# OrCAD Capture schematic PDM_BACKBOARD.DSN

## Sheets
1 bb_outline: title: Photo Detector Module's backboard; rev: 1.0; note: BB_outline; note: INFN-Ferrara / INFN Milano-Bicocca; note: designer: Angelo Cotta Ramusino
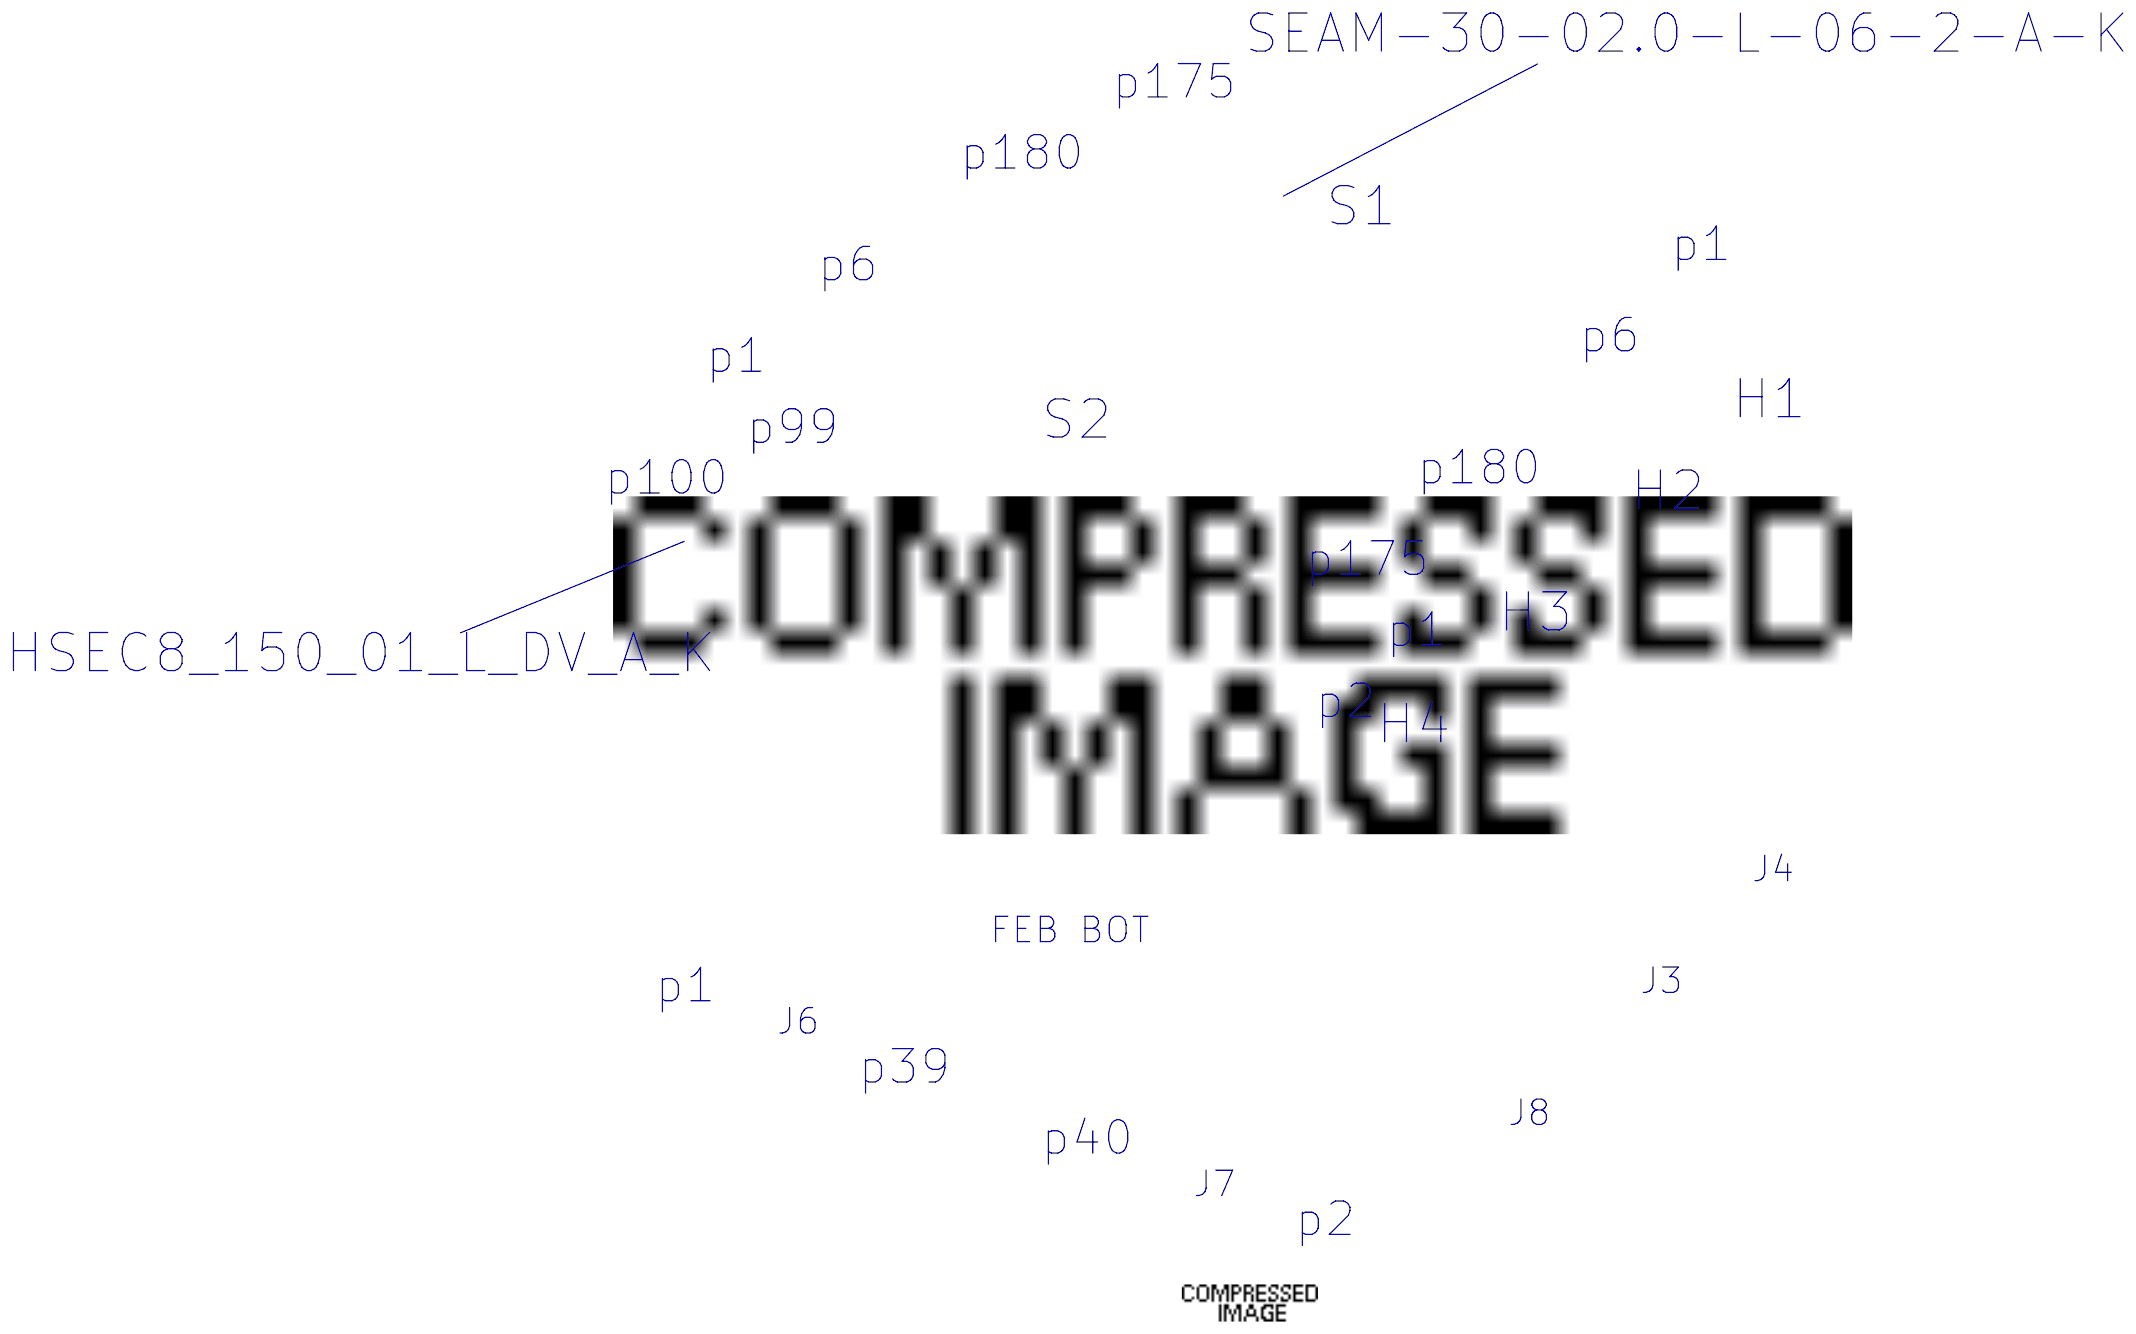
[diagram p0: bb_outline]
2 bb_main: size B; note: BB_sch_main
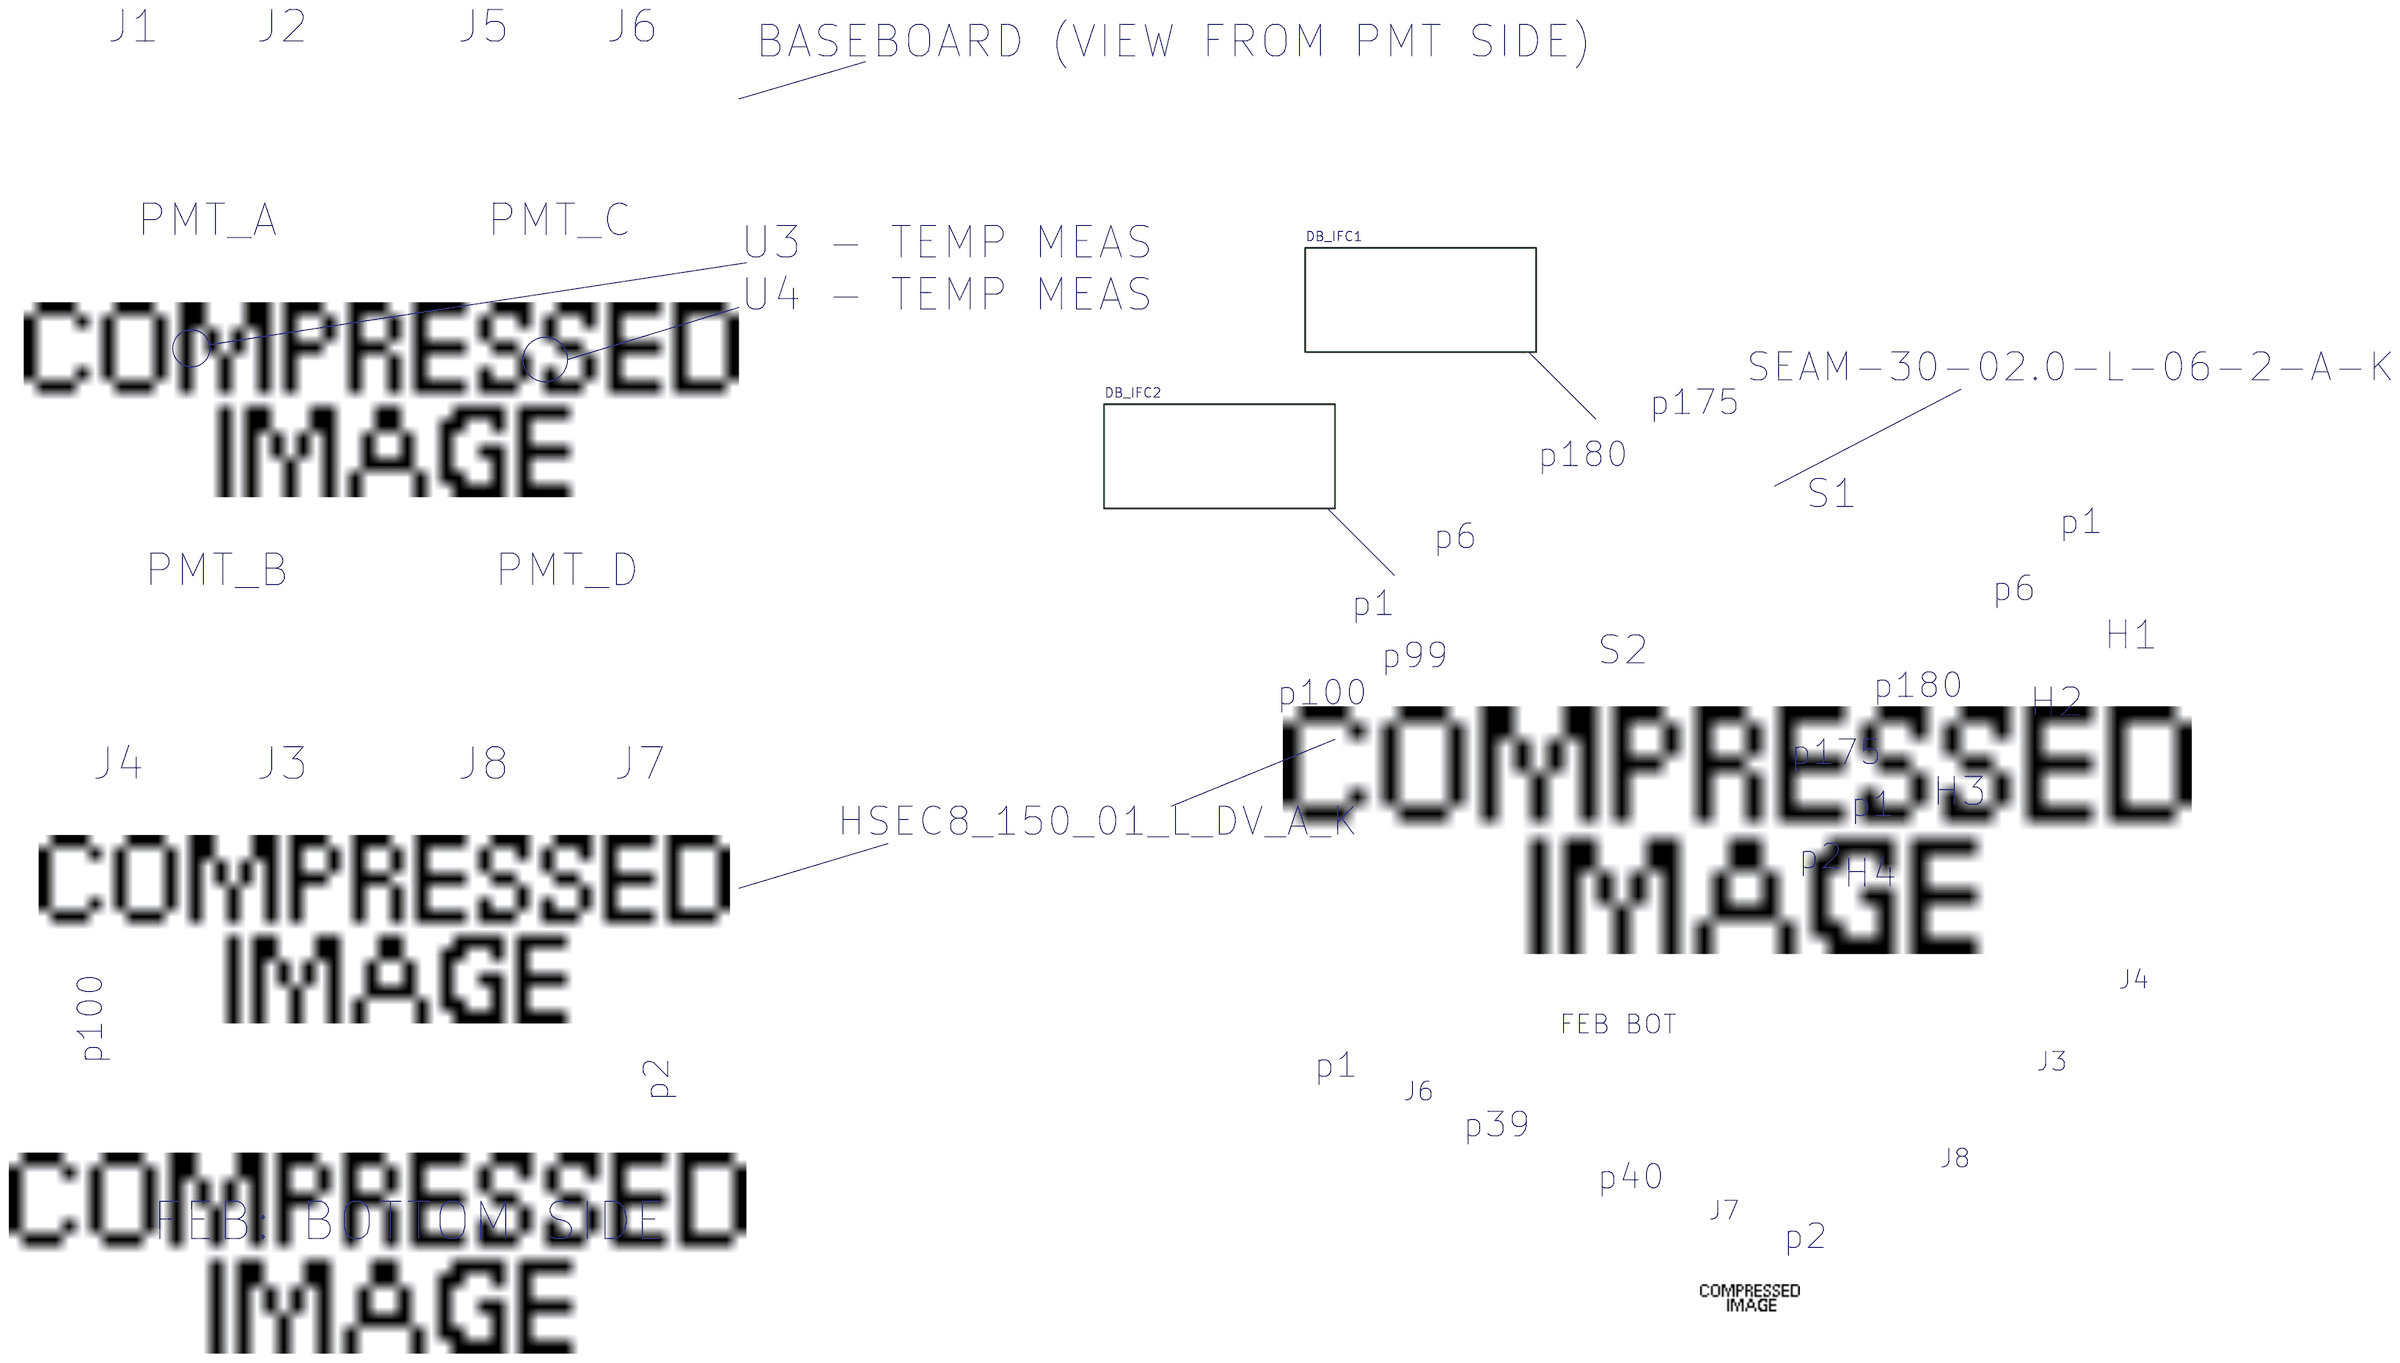
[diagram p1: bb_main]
3 DB_Interface_1: size B; note: DB_Interface_1; note: designer: A. Cotta Ramusino, C. Gotti; block DB_IFC1
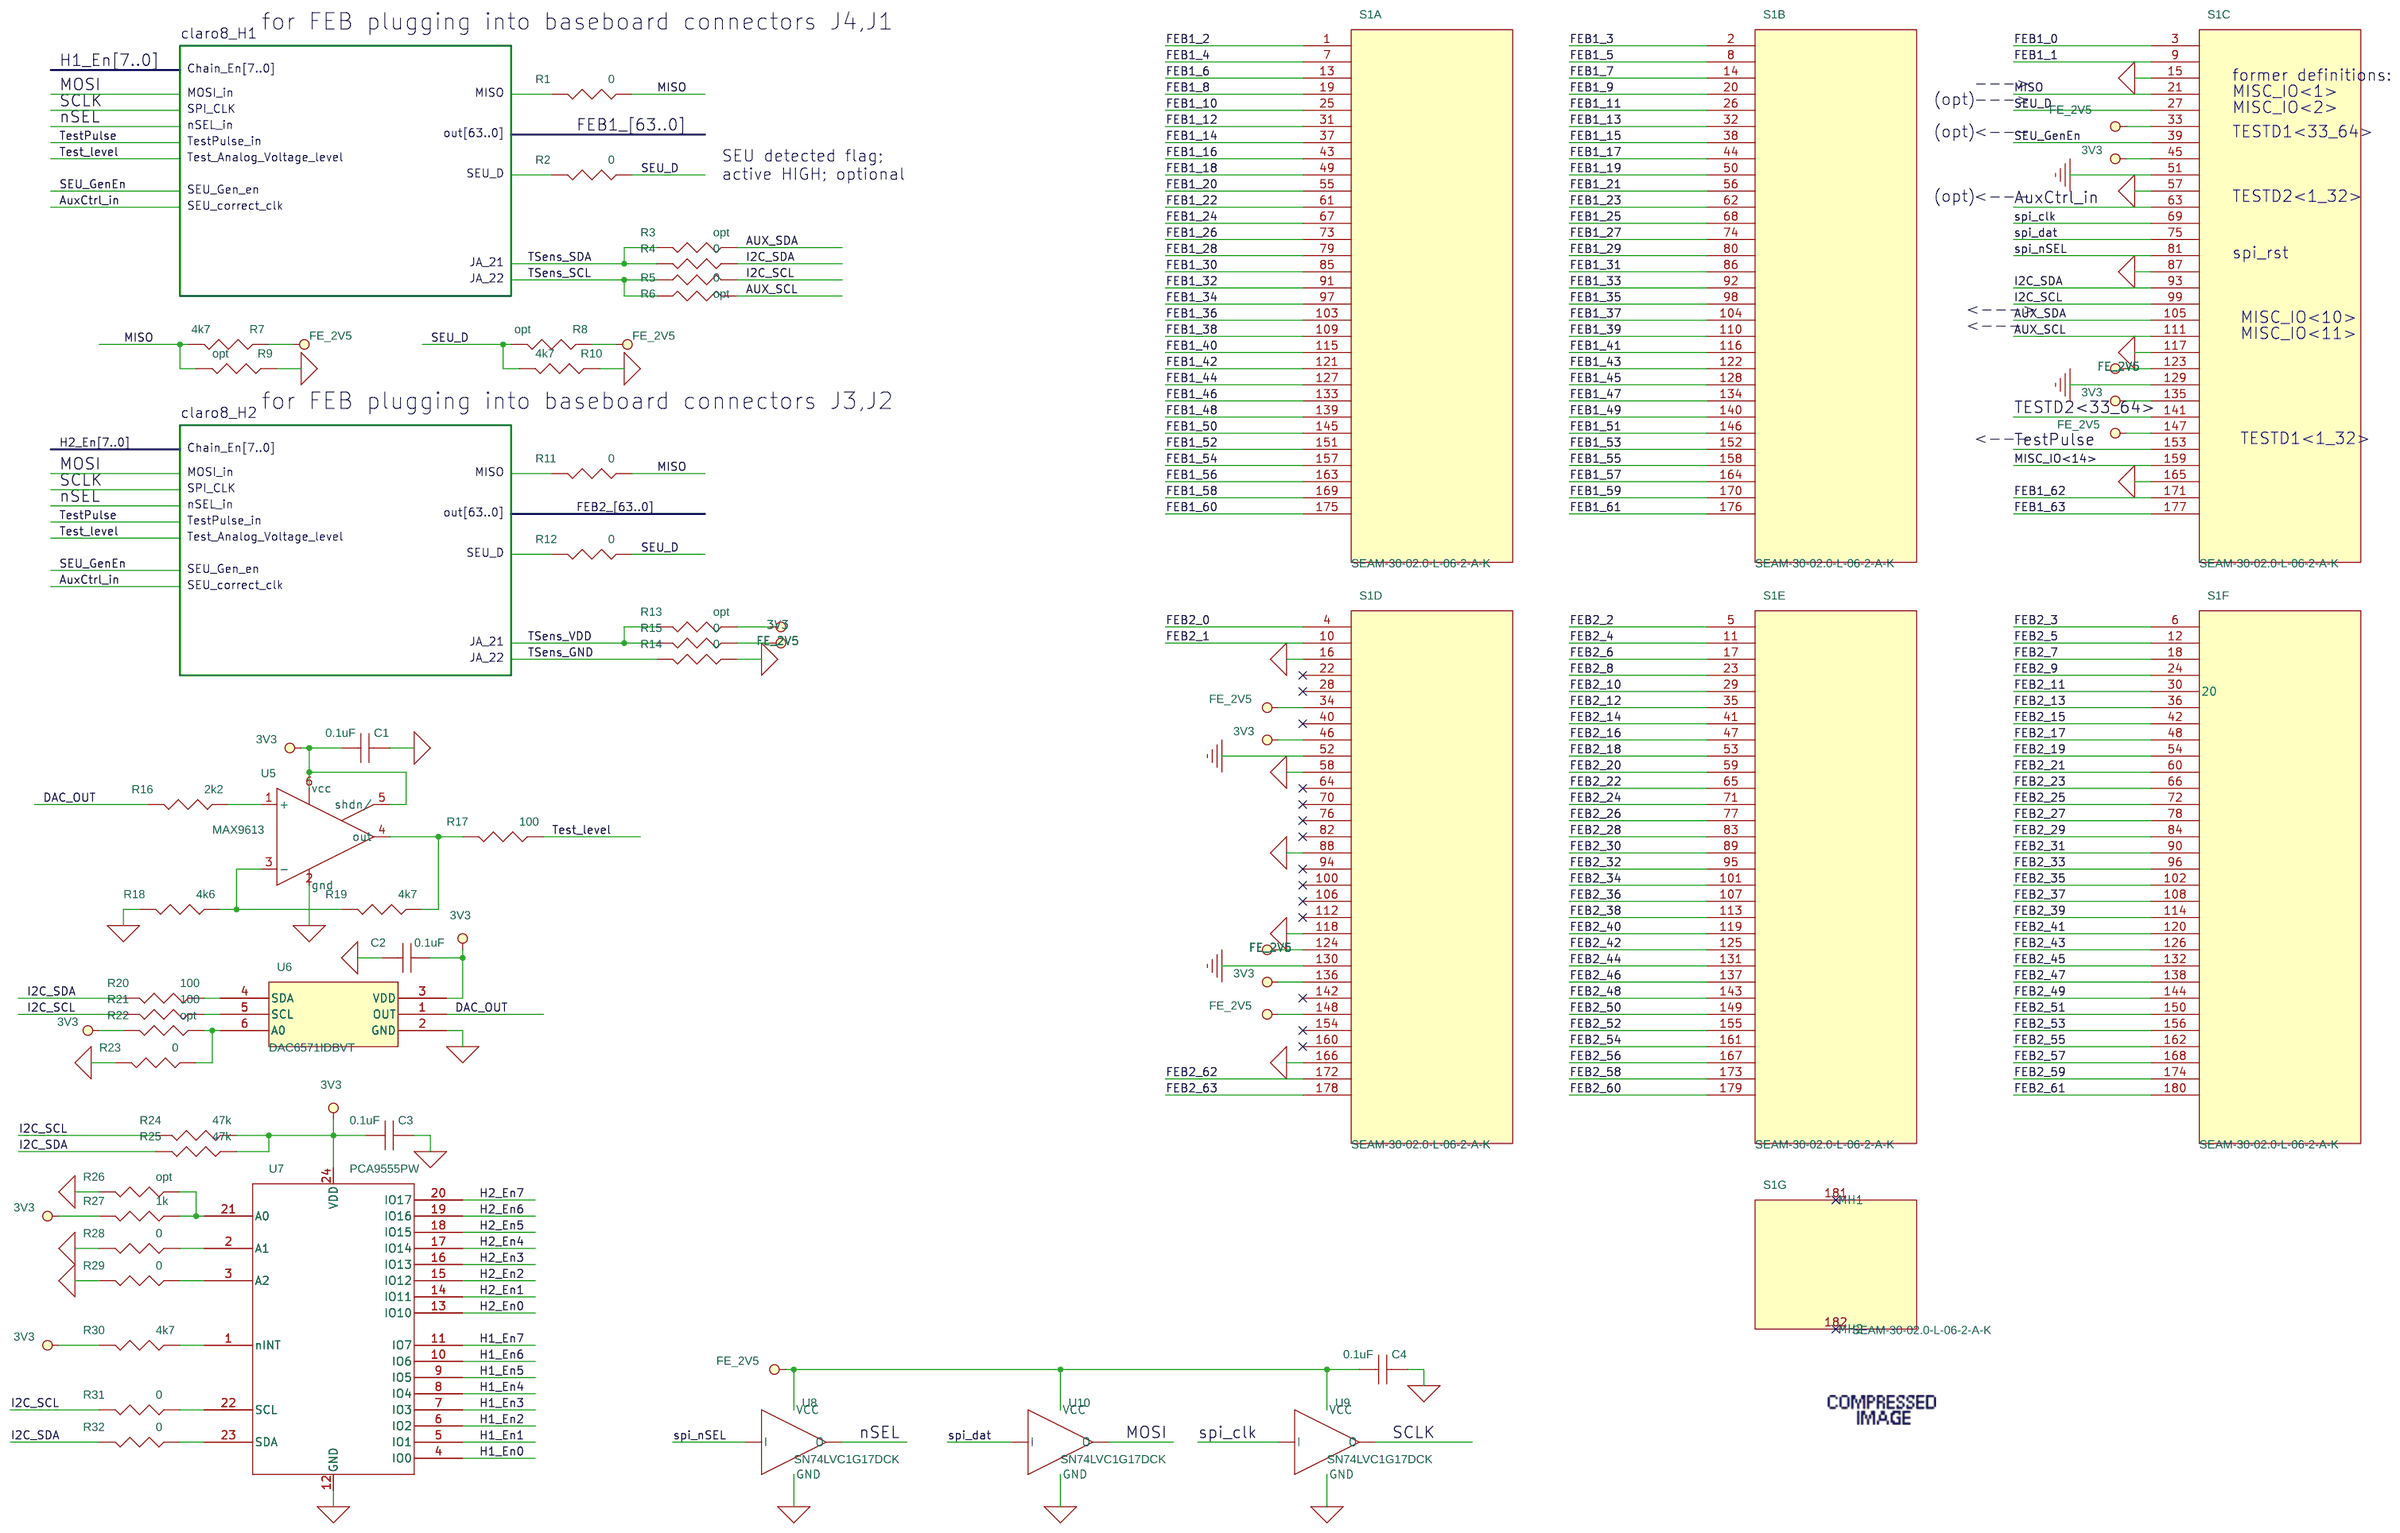
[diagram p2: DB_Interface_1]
4 claro8_interface: size A; note: backboard_to_FEB_interface; block DB_IFC1/claro8_H2
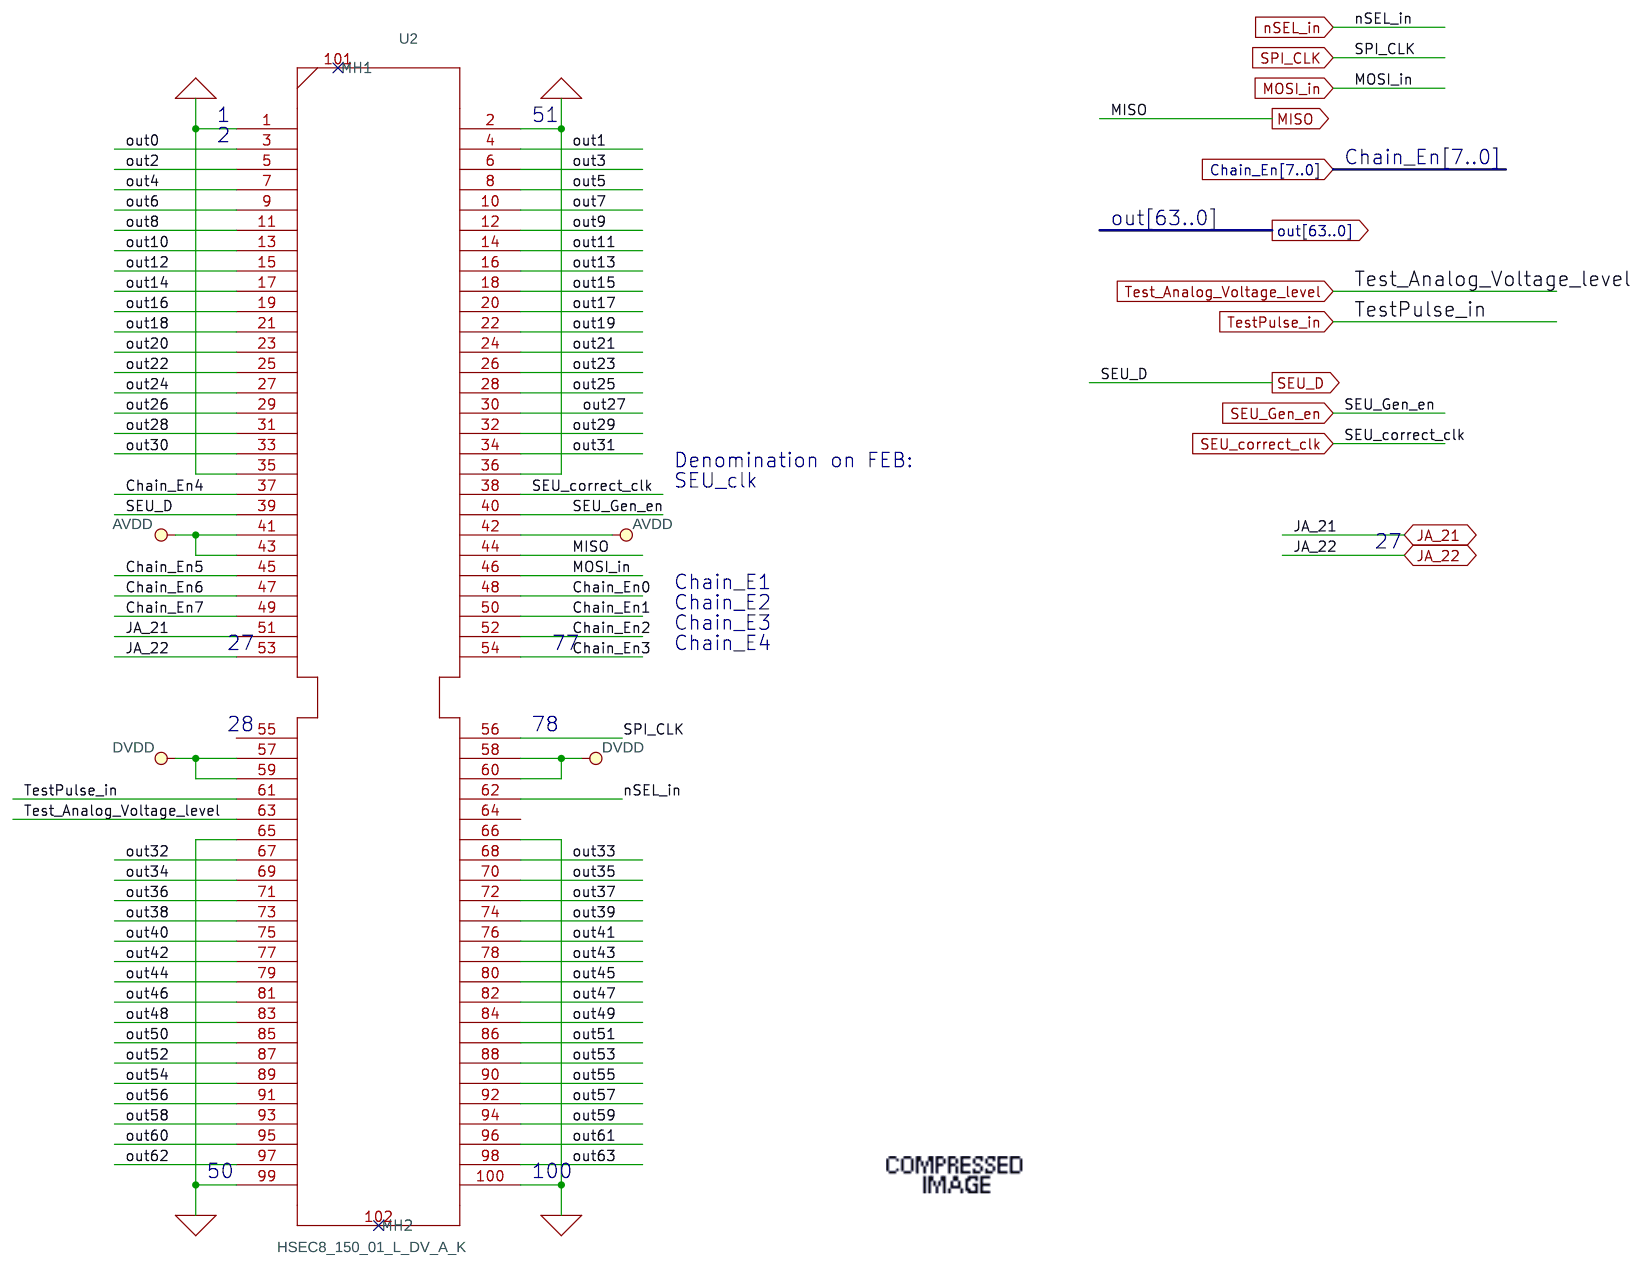
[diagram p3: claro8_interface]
5 claro8_interface (2): block DB_IFC1/claro8_H1, another copy of sheet 4
6 DB_Interface_2: size B; note: DB_Interface_2; note: designer: A. Cotta Ramusino, C. Gotti; block DB_IFC2
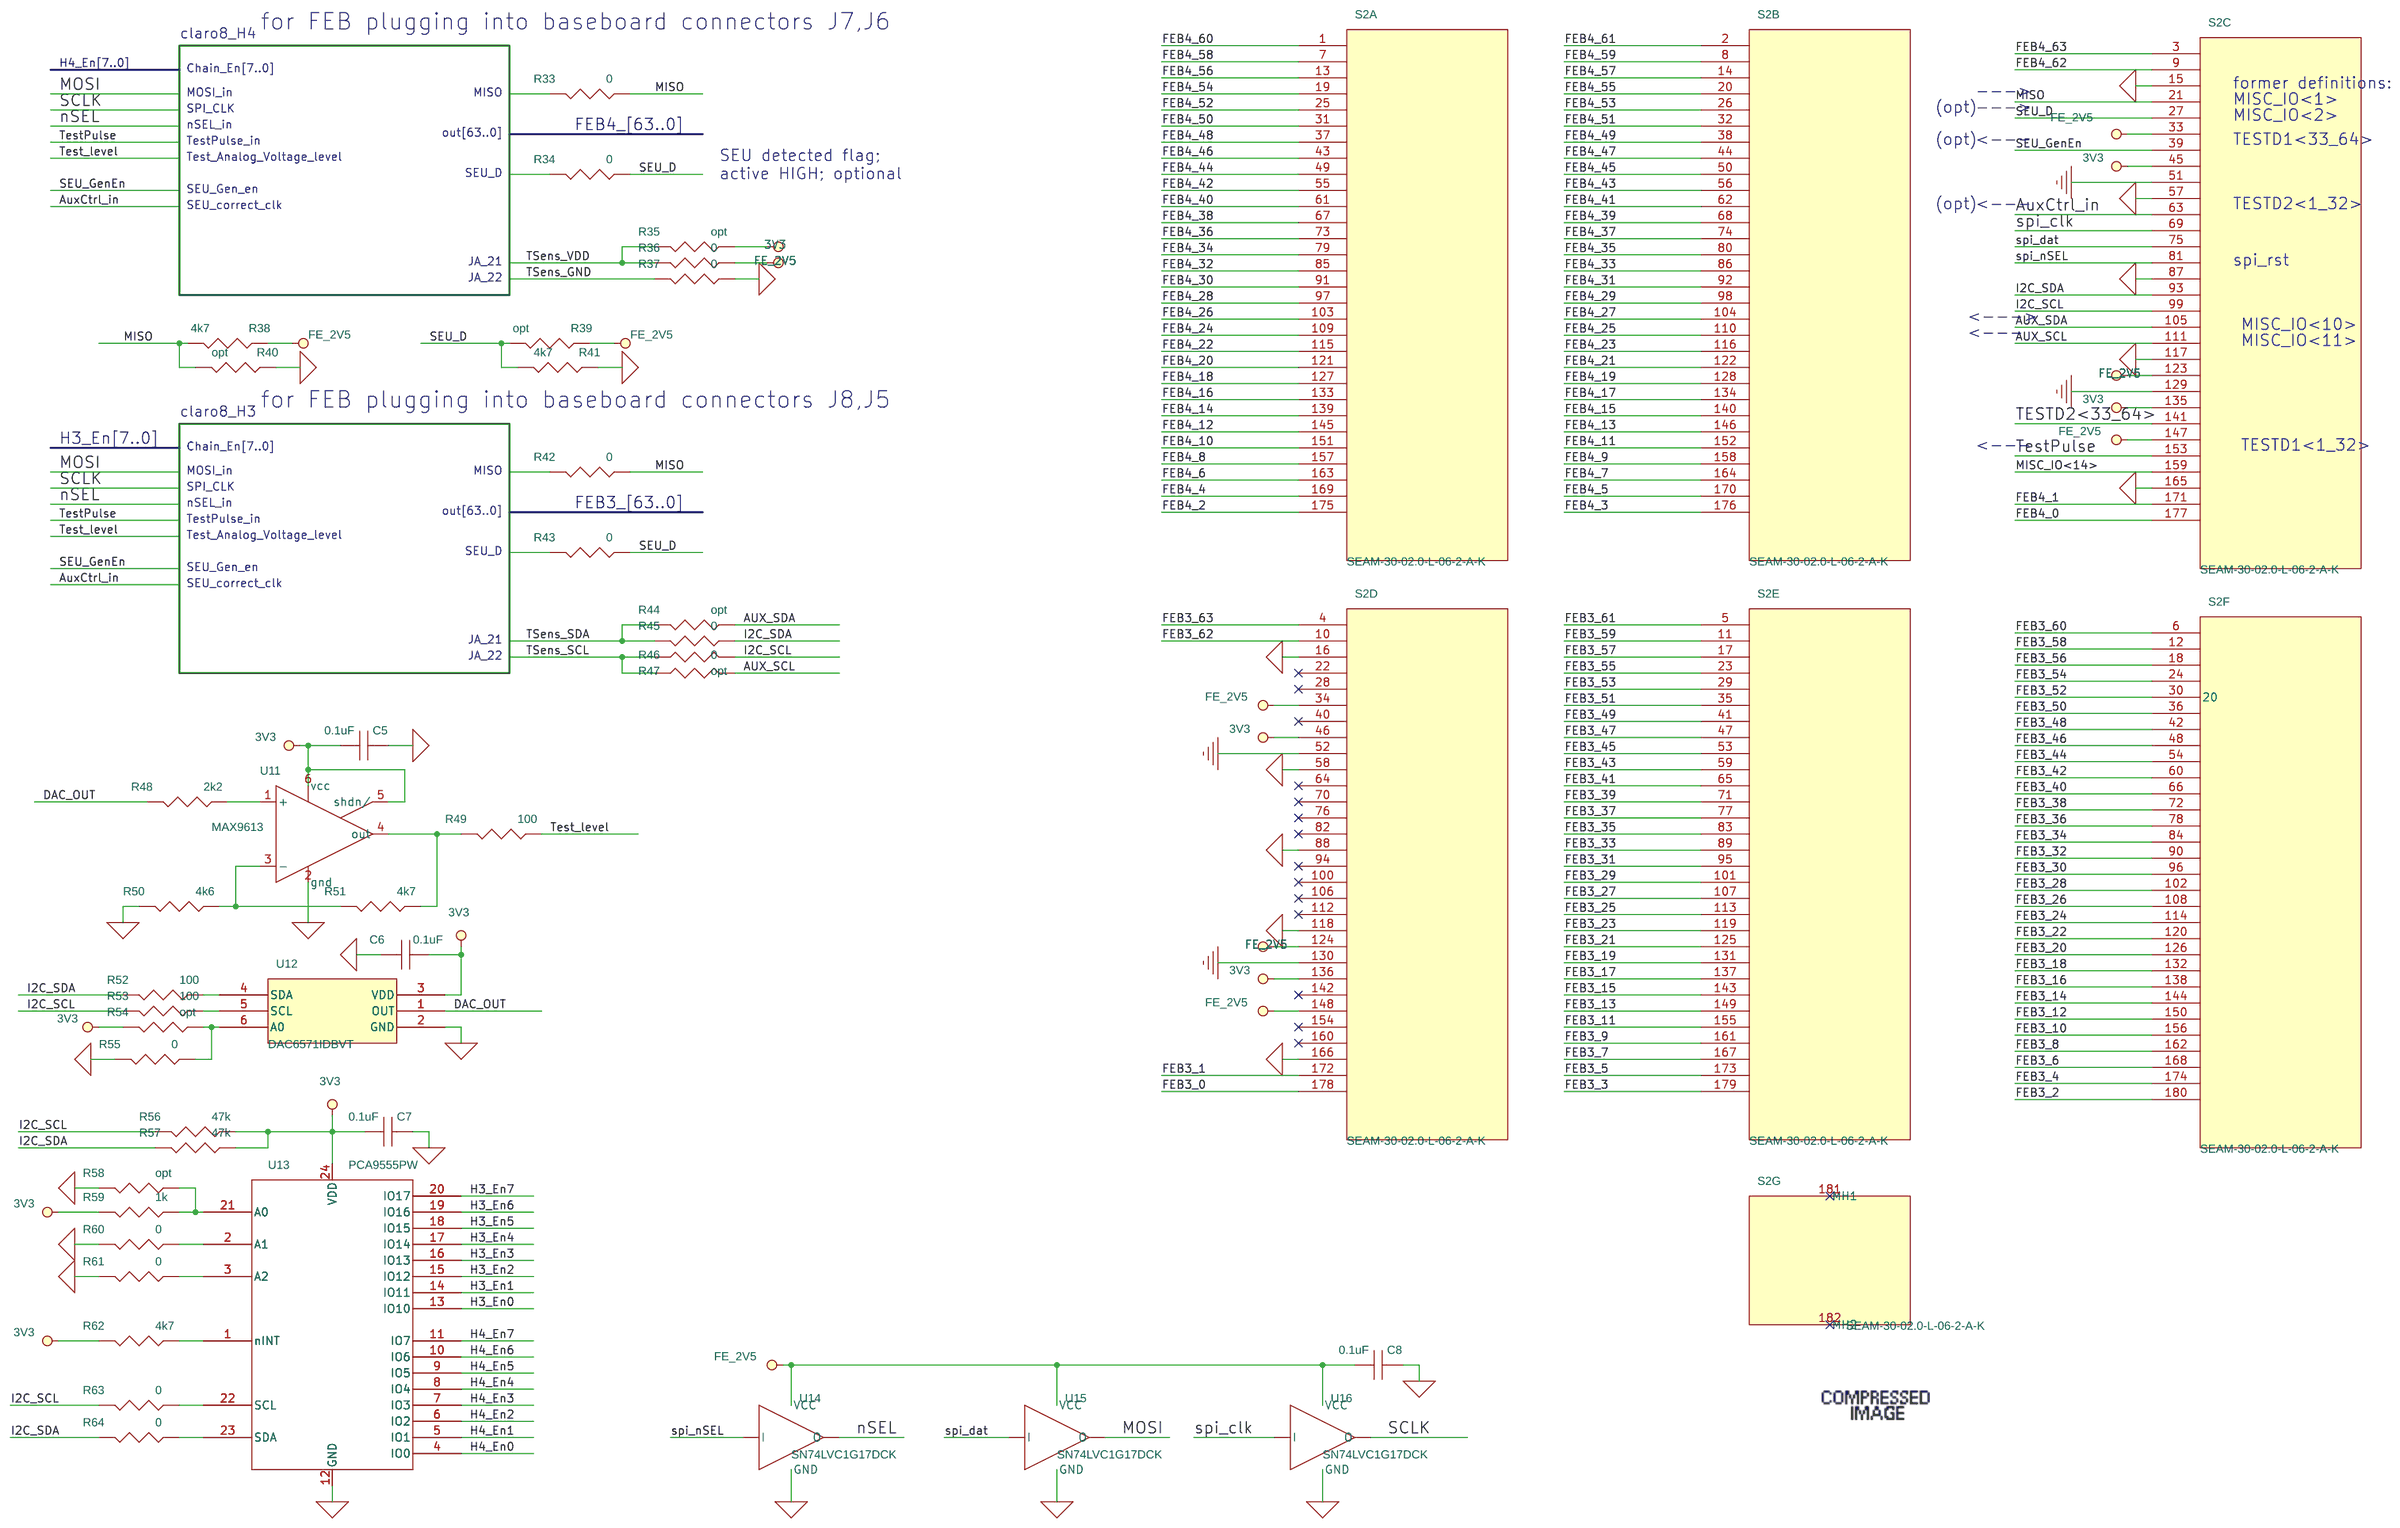
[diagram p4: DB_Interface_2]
7 claro8_interface (3): block DB_IFC2/claro8_H4, another copy of sheet 4
8 claro8_interface (4): block DB_IFC2/claro8_H3, another copy of sheet 4

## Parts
sheet claro8_interface (2)
U1  HSEC8_150_01_L_DV_A_K  [HSEC8_150_01_L_DV_A_K]
sheet claro8_interface (3)
U4  HSEC8_150_01_L_DV_A_K  [HSEC8_150_01_L_DV_A_K]
sheet claro8_interface (4)
U3  HSEC8_150_01_L_DV_A_K  [HSEC8_150_01_L_DV_A_K]
sheet claro8_interface
U2  HSEC8_150_01_L_DV_A_K  [HSEC8_150_01_L_DV_A_K]
sheet DB_Interface_1
C1  0.1uF  [0402]
C2  0.1uF  [0402]
C3  0.1uF  [0402]
C4  0.1uF  [0402]
R1  0  [0402]
R2  0  [0402]
R3  opt  [0402]
R4  0  [0402]
R5  0  [0402]
R6  opt  [0402]
R7  4k7  [0402]
R8  opt  [0402]
R9  opt  [0402]
R10  4k7  [0402]
R11  0  [0402]
R12  0  [0402]
R13  opt  [0402]
R14  0  [0402]
R15  0  [0402]
R16  2k2  [0402]
R17  100  [0402]
R18  4k6  [0402]
R19  4k7  [0402]
R20  100  [0402]
R21  100  [0402]
R22  opt  [0402]
R23  0  [0402]
R24  47k  [0402]
R25  47k  [0402]
R26  opt  [0402]
R27  1k  [0402]
R28  0  [0402]
R29  0  [0402]
R30  4k7  [0402]
R31  0  [0402]
R32  0  [0402]
S1  SEAM-30-02.0-L-06-2-A-K  (sections A,B,C,D,E,F,G)
U5  MAX9613  [SC70_6]
U6  DAC6571IDBVT  [SOT23-6]
U7  PCA9555PW  [TSSOP24]
U8  SN74LVC1G17DCK  [SC70_5]
U9  SN74LVC1G17DCK  [SC70_5]
U10  SN74LVC1G17DCK  [SC70_5]
sheet DB_Interface_2
C5  0.1uF  [0402]
C6  0.1uF  [0402]
C7  0.1uF  [0402]
C8  0.1uF  [0402]
R33  0  [0402]
R34  0  [0402]
R35  opt  [0402]
R36  0  [0402]
R37  0  [0402]
R38  4k7  [0402]
R39  opt  [0402]
R40  opt  [0402]
R41  4k7  [0402]
R42  0  [0402]
R43  0  [0402]
R44  opt  [0402]
R45  0  [0402]
R46  0  [0402]
R47  opt  [0402]
R48  2k2  [0402]
R49  100  [0402]
R50  4k6  [0402]
R51  4k7  [0402]
R52  100  [0402]
R53  100  [0402]
R54  opt  [0402]
R55  0  [0402]
R56  47k  [0402]
R57  47k  [0402]
R58  opt  [0402]
R59  1k  [0402]
R60  0  [0402]
R61  0  [0402]
R62  4k7  [0402]
R63  0  [0402]
R64  0  [0402]
S2  SEAM-30-02.0-L-06-2-A-K  (sections A,B,C,D,E,F,G)
U11  MAX9613  [SC70_6]
U12  DAC6571IDBVT  [SOT23-6]
U13  PCA9555PW  [TSSOP24]
U14  SN74LVC1G17DCK  [SC70_5]
U15  SN74LVC1G17DCK  [SC70_5]
U16  SN74LVC1G17DCK  [SC70_5]

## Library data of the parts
U1-U4 = HSEC8_150_01_L_DV_A_K_1
C1-C8 = CAP: CAP - CERAMIC,  0.1UF 0402 25VDC Y5V; AGILE_LINK: http://sj-agile9app/Agile/PLMServlet?action=OpenEmailObject&classid=10000&objid=213459527; Item Num: P03-15057R; LIFECYCLE_PHASE: Active; Lead Free Status: Lead Free; MFR_LIFECYCLE: Active; Manufacturer: Murata; Manufacturer Part Num: GRM155F51E104ZA01D; Num Pins: 2; PART_SUBCLASS: CAPACITORS; RATED_VOLTAGE: 25V; RoHS Compliant: RoHS Compliant; TOLERANCE: +80%/-20%
R1 R2 R4 R5 R11 R12 R14 R15 R23 R28 R29 R31-R34 R36 R37 R42 R43 R45 R46 R55 R60 R61 R63 R64 = R: RES, 4700 OHMS, 1%, 1/16W, 0402; Lead Free Status: Yes; Manufacturer: NIC Components Corp.; Manufacturer Part Num: NRC04F49R9TRF; Num Pins: 2; Part Class: Resistors
R3 R6-R10 R13 R16-R22 R24-R27 R30 R35 R38-R41 R44 R47-R54 R56-R59 R62 = R: RES, 4700 OHMS, 1%, 1/16W, 0402; Lead Free Status: Yes; Manufacturer: NIC Components Corp.; Manufacturer Part Num: NRC04F49R9TRF; Num Pins: 2; Part Class: Resistors; Price: 0
S1 S2 = SEAM-30-02.0-L-06-2-A-K
U5 U11 = MAX9613
U6 U12 = DAC6571IDBVT
U7 U13 = PCA9554_1: MFR_Code: NXP PCA9554PW
U8-U10 U14-U16 = SN74LVC1G17DCK

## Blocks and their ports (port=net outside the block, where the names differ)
DB_IFC2 = schematic DB_Interface_2, on sheet bb_main: no ports
DB_IFC2/claro8_H3 = schematic claro8_interface, on sheet DB_Interface_2: SEU_Gen_en=DB_IFC2/SEU_GenEn, MOSI_in=DB_IFC2/MOSI, JA_21=DB_IFC2/TSens_SDA, JA_22=DB_IFC2/TSens_SCL, nSEL_in=DB_IFC2/nSEL, SPI_CLK=DB_IFC2/SCLK, out[63..0]=FEB3_[63..0], SEU_correct_clk=DB_IFC2/AuxCtrl_in, MISO=DB_IFC2/N13982825, Test_Analog_Voltage_level=DB_IFC2/Test_level, SEU_D=DB_IFC2/N13982847, Chain_En[7..0]=H3_EN[7..0], TestPulse_in=DB_IFC2/TestPulse
DB_IFC2/claro8_H4 = schematic claro8_interface, on sheet DB_Interface_2: SEU_Gen_en=DB_IFC2/SEU_GenEn, MOSI_in=DB_IFC2/MOSI, JA_21=DB_IFC2/TSens_VDD, JA_22=DB_IFC2/TSens_GND, nSEL_in=DB_IFC2/nSEL, SPI_CLK=DB_IFC2/SCLK, out[63..0]=FEB4_[63..0], SEU_correct_clk=DB_IFC2/AuxCtrl_in, MISO=DB_IFC2/N13982301, Test_Analog_Voltage_level=DB_IFC2/Test_level, SEU_D=DB_IFC2/N13982797, Chain_En[7..0]=H4_EN[7..0], TestPulse_in=DB_IFC2/TestPulse
DB_IFC1 = schematic DB_Interface_1, on sheet bb_main: no ports
DB_IFC1/claro8_H2 = schematic claro8_interface, on sheet DB_Interface_1: SEU_Gen_en=DB_IFC1/SEU_GenEn, MOSI_in=DB_IFC1/MOSI, JA_21=DB_IFC1/TSens_VDD, JA_22=DB_IFC1/TSens_GND, nSEL_in=DB_IFC1/nSEL, SPI_CLK=DB_IFC1/SCLK, out[63..0]=FEB2_[63..0], SEU_correct_clk=DB_IFC1/AuxCtrl_in, MISO=DB_IFC1/N13975140, Test_Analog_Voltage_level=DB_IFC1/Test_level, SEU_D=DB_IFC1/N13975216, Chain_En[7..0]=H2_EN[7..0], TestPulse_in=DB_IFC1/TestPulse
DB_IFC1/claro8_H1 = schematic claro8_interface, on sheet DB_Interface_1: SEU_Gen_en=DB_IFC1/SEU_GenEn, MOSI_in=DB_IFC1/MOSI, JA_21=DB_IFC1/TSens_SDA, JA_22=DB_IFC1/TSens_SCL, nSEL_in=DB_IFC1/nSEL, SPI_CLK=DB_IFC1/SCLK, out[63..0]=FEB1_[63..0], SEU_correct_clk=DB_IFC1/AuxCtrl_in, MISO=DB_IFC1/N13947191, Test_Analog_Voltage_level=DB_IFC1/Test_level, SEU_D=DB_IFC1/N13966514, Chain_En[7..0]=H1_EN[7..0], TestPulse_in=DB_IFC1/TestPulse

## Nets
3V3: C1.1 C2.1 C3.1 C5.1 C6.1 C7.1 R13.2 R22.1 R24.2 R25.2 R27.1 R30.1 R35.2 R54.1 R56.2 R57.2 R59.1 R62.1 S1.45 S1.46 S1.135 S1.136 S2.45 S2.46 S2.135 S2.136 U5.5(shdn/) U5.6(vcc) U6.3(VDD) U7.24(VDD) U11.5(shdn/) U11.6(vcc) U12.3(VDD) U13.24(VDD)
avdd: U1.41 U1.42 U1.43 U2.41 U2.42 U2.43 U3.41 U3.42 U3.43 U4.41 U4.42 U4.43
dvdd: U1.57 U1.58 U1.59 U1.60 U2.57 U2.58 U2.59 U2.60 U3.57 U3.58 U3.59 U3.60 U4.57 U4.58 U4.59 U4.60
GND_FE: C1.2 C2.2 C3.2 C4.2 C5.2 C6.2 C7.2 C8.2 R9.1 R10.1 R14.2 R18.1 R23.1 R26.1 R28.1 R29.1 R37.2 R40.1 R41.1 R50.1 R55.1 R58.1 R60.1 R61.1 S1.15 S1.16 S1.57 S1.58 S1.87 S1.88 S1.117 S1.118 S1.165 S1.166 S2.15 S2.16 S2.57 S2.58 S2.87 S2.88 S2.117 S2.118 S2.165 S2.166 U1.1 U1.2 U1.35 U1.36 U1.65 U1.66 U1.99 U1.100 U2.1 U2.2 U2.35 U2.36 U2.65 U2.66 U2.99 U2.100 U3.1 U3.2 U3.35 U3.36 U3.65 U3.66 U3.99 U3.100 U4.1 U4.2 U4.35 U4.36 U4.65 U4.66 U4.99 U4.100 U5.2(gnd) U6.2(GND) U7.12(GND) U8.3(GND) U9.3(GND) U10.3(GND) U11.2(gnd) U12.2(GND) U13.12(GND) U14.3(GND) U15.3(GND) U16.3(GND)
GND_POWER: S1.51 S1.52 S1.129 S1.130 S2.51 S2.52 S2.129 S2.130
DB_IFC1/AUX_SCL: R6.2 S1.111
DB_IFC1/AUX_SDA: R3.2 S1.105
DB_IFC1/AuxCtrl_in: S1.63 U1.38 U2.38
DB_IFC1/DAC_OUT: R16.1 U6.1(OUT)
DB_IFC1/FEB1_0: S1.3 U1.3
DB_IFC1/FEB1_1: S1.9 U1.4
DB_IFC1/FEB1_2: S1.1 U1.5
DB_IFC1/FEB1_3: S1.2 U1.6
DB_IFC1/FEB1_4: S1.7 U1.7
DB_IFC1/FEB1_5: S1.8 U1.8
DB_IFC1/FEB1_6: S1.13 U1.9
DB_IFC1/FEB1_7: S1.14 U1.10
DB_IFC1/FEB1_8: S1.19 U1.11
DB_IFC1/FEB1_9: S1.20 U1.12
DB_IFC1/FEB1_10: S1.25 U1.13
DB_IFC1/FEB1_11: S1.26 U1.14
DB_IFC1/FEB1_12: S1.31 U1.15
DB_IFC1/FEB1_13: S1.32 U1.16
DB_IFC1/FEB1_14: S1.37 U1.17
DB_IFC1/FEB1_15: S1.38 U1.18
DB_IFC1/FEB1_16: S1.43 U1.19
DB_IFC1/FEB1_17: S1.44 U1.20
DB_IFC1/FEB1_18: S1.49 U1.21
DB_IFC1/FEB1_19: S1.50 U1.22
DB_IFC1/FEB1_20: S1.55 U1.23
DB_IFC1/FEB1_21: S1.56 U1.24
DB_IFC1/FEB1_22: S1.61 U1.25
DB_IFC1/FEB1_23: S1.62 U1.26
DB_IFC1/FEB1_24: S1.67 U1.27
DB_IFC1/FEB1_25: S1.68 U1.28
DB_IFC1/FEB1_26: S1.73 U1.29
DB_IFC1/FEB1_27: S1.74 U1.30
DB_IFC1/FEB1_28: S1.79 U1.31
DB_IFC1/FEB1_29: S1.80 U1.32
DB_IFC1/FEB1_30: S1.85 U1.33
DB_IFC1/FEB1_31: S1.86 U1.34
DB_IFC1/FEB1_32: S1.91 U1.67
DB_IFC1/FEB1_33: S1.92 U1.68
DB_IFC1/FEB1_34: S1.97 U1.69
DB_IFC1/FEB1_35: S1.98 U1.70
DB_IFC1/FEB1_36: S1.103 U1.71
DB_IFC1/FEB1_37: S1.104 U1.72
DB_IFC1/FEB1_38: S1.109 U1.73
DB_IFC1/FEB1_39: S1.110 U1.74
DB_IFC1/FEB1_40: S1.115 U1.75
DB_IFC1/FEB1_41: S1.116 U1.76
DB_IFC1/FEB1_42: S1.121 U1.77
DB_IFC1/FEB1_43: S1.122 U1.78
DB_IFC1/FEB1_44: S1.127 U1.79
DB_IFC1/FEB1_45: S1.128 U1.80
DB_IFC1/FEB1_46: S1.133 U1.81
DB_IFC1/FEB1_47: S1.134 U1.82
DB_IFC1/FEB1_48: S1.139 U1.83
DB_IFC1/FEB1_49: S1.140 U1.84
DB_IFC1/FEB1_50: S1.145 U1.85
DB_IFC1/FEB1_51: S1.146 U1.86
DB_IFC1/FEB1_52: S1.151 U1.87
DB_IFC1/FEB1_53: S1.152 U1.88
DB_IFC1/FEB1_54: S1.157 U1.89
DB_IFC1/FEB1_55: S1.158 U1.90
DB_IFC1/FEB1_56: S1.163 U1.91
DB_IFC1/FEB1_57: S1.164 U1.92
DB_IFC1/FEB1_58: S1.169 U1.93
DB_IFC1/FEB1_59: S1.170 U1.94
DB_IFC1/FEB1_60: S1.175 U1.95
DB_IFC1/FEB1_61: S1.176 U1.96
DB_IFC1/FEB1_62: S1.171 U1.97
DB_IFC1/FEB1_63: S1.177 U1.98
DB_IFC1/FEB2_0: S1.4 U2.3
DB_IFC1/FEB2_1: S1.10 U2.4
DB_IFC1/FEB2_2: S1.5 U2.5
DB_IFC1/FEB2_3: S1.6 U2.6
DB_IFC1/FEB2_4: S1.11 U2.7
DB_IFC1/FEB2_5: S1.12 U2.8
DB_IFC1/FEB2_6: S1.17 U2.9
DB_IFC1/FEB2_7: S1.18 U2.10
DB_IFC1/FEB2_8: S1.23 U2.11
DB_IFC1/FEB2_9: S1.24 U2.12
DB_IFC1/FEB2_10: S1.29 U2.13
DB_IFC1/FEB2_11: S1.30(20) U2.14
DB_IFC1/FEB2_12: S1.35 U2.15
DB_IFC1/FEB2_13: S1.36 U2.16
DB_IFC1/FEB2_14: S1.41 U2.17
DB_IFC1/FEB2_15: S1.42 U2.18
DB_IFC1/FEB2_16: S1.47 U2.19
DB_IFC1/FEB2_17: S1.48 U2.20
DB_IFC1/FEB2_18: S1.53 U2.21
DB_IFC1/FEB2_19: S1.54 U2.22
DB_IFC1/FEB2_20: S1.59 U2.23
DB_IFC1/FEB2_21: S1.60 U2.24
DB_IFC1/FEB2_22: S1.65 U2.25
DB_IFC1/FEB2_23: S1.66 U2.26
DB_IFC1/FEB2_24: S1.71 U2.27
DB_IFC1/FEB2_25: S1.72 U2.28
DB_IFC1/FEB2_26: S1.77 U2.29
DB_IFC1/FEB2_27: S1.78 U2.30
DB_IFC1/FEB2_28: S1.83 U2.31
DB_IFC1/FEB2_29: S1.84 U2.32
DB_IFC1/FEB2_30: S1.89 U2.33
DB_IFC1/FEB2_31: S1.90 U2.34
DB_IFC1/FEB2_32: S1.95 U2.67
DB_IFC1/FEB2_33: S1.96 U2.68
DB_IFC1/FEB2_34: S1.101 U2.69
DB_IFC1/FEB2_35: S1.102 U2.70
DB_IFC1/FEB2_36: S1.107 U2.71
DB_IFC1/FEB2_37: S1.108 U2.72
DB_IFC1/FEB2_38: S1.113 U2.73
DB_IFC1/FEB2_39: S1.114 U2.74
DB_IFC1/FEB2_40: S1.119 U2.75
DB_IFC1/FEB2_41: S1.120 U2.76
DB_IFC1/FEB2_42: S1.125 U2.77
DB_IFC1/FEB2_43: S1.126 U2.78
DB_IFC1/FEB2_44: S1.131 U2.79
DB_IFC1/FEB2_45: S1.132 U2.80
DB_IFC1/FEB2_46: S1.137 U2.81
DB_IFC1/FEB2_47: S1.138 U2.82
DB_IFC1/FEB2_48: S1.143 U2.83
DB_IFC1/FEB2_49: S1.144 U2.84
DB_IFC1/FEB2_50: S1.149 U2.85
DB_IFC1/FEB2_51: S1.150 U2.86
DB_IFC1/FEB2_52: S1.155 U2.87
DB_IFC1/FEB2_53: S1.156 U2.88
DB_IFC1/FEB2_54: S1.161 U2.89
DB_IFC1/FEB2_55: S1.162 U2.90
DB_IFC1/FEB2_56: S1.167 U2.91
DB_IFC1/FEB2_57: S1.168 U2.92
DB_IFC1/FEB2_58: S1.173 U2.93
DB_IFC1/FEB2_59: S1.174 U2.94
DB_IFC1/FEB2_60: S1.179 U2.95
DB_IFC1/FEB2_61: S1.180 U2.96
DB_IFC1/FEB2_62: S1.172 U2.97
DB_IFC1/FEB2_63: S1.178 U2.98
DB_IFC1/H1_En0: U1.48 U7.4(IO0)
DB_IFC1/H1_En1: U1.50 U7.5(IO1)
DB_IFC1/H1_En2: U1.52 U7.6(IO2)
DB_IFC1/H1_En3: U1.54 U7.7(IO3)
DB_IFC1/H1_En4: U1.37 U7.8(IO4)
DB_IFC1/H1_En5: U1.45 U7.9(IO5)
DB_IFC1/H1_En6: U1.47 U7.10(IO6)
DB_IFC1/H1_En7: U1.49 U7.11(IO7)
DB_IFC1/H2_En0: U2.48 U7.13(IO10)
DB_IFC1/H2_En1: U2.50 U7.14(IO11)
DB_IFC1/H2_En2: U2.52 U7.15(IO12)
DB_IFC1/H2_En3: U2.54 U7.16(IO13)
DB_IFC1/H2_En4: U2.37 U7.17(IO14)
DB_IFC1/H2_En5: U2.45 U7.18(IO15)
DB_IFC1/H2_En6: U2.47 U7.19(IO16)
DB_IFC1/H2_En7: U2.49 U7.20(IO17)
DB_IFC1/I2C_SCL: R5.2 R21.1 R24.1 R31.1 S1.99
DB_IFC1/I2C_SDA: R4.2 R20.1 R25.1 R32.1 S1.93
DB_IFC1/MISC_IO<14>: S1.159
DB_IFC1/MISO: R1.2 R7.2 R9.2 R11.2 S1.21
DB_IFC1/MOSI: U1.46 U2.46 U10.4(O)
DB_IFC1/nSEL: U1.62 U2.62 U8.4(O)
DB_IFC1/SCLK: U1.56 U2.56 U9.4(O)
DB_IFC1/SEU_D: R2.2 R8.2 R10.2 R12.2 S1.27
DB_IFC1/SEU_GenEn: S1.39 U1.40 U2.40
DB_IFC1/spi_clk: S1.69 U9.2(I)
DB_IFC1/spi_dat: S1.75 U10.2(I)
DB_IFC1/spi_nSEL: S1.81 U8.2(I)
DB_IFC1/Test_level: R17.2 U1.63 U2.63
DB_IFC1/TESTD2<33_64>: S1.141
DB_IFC1/TestPulse: S1.153 U1.61 U2.61
DB_IFC1/TSens_GND: R14.1 U2.53
DB_IFC1/TSens_SCL: R5.1 R6.1 U1.53
DB_IFC1/TSens_SDA: R3.1 R4.1 U1.51
DB_IFC1/TSens_VDD: R13.1 R15.1 U2.51
DB_IFC2/AUX_SCL: R47.2 S2.111
DB_IFC2/AUX_SDA: R44.2 S2.105
DB_IFC2/AuxCtrl_in: S2.63 U3.38 U4.38
DB_IFC2/DAC_OUT: R48.1 U12.1(OUT)
DB_IFC2/FEB3_0: S2.178 U3.3
DB_IFC2/FEB3_1: S2.172 U3.4
DB_IFC2/FEB3_2: S2.180 U3.5
DB_IFC2/FEB3_3: S2.179 U3.6
DB_IFC2/FEB3_4: S2.174 U3.7
DB_IFC2/FEB3_5: S2.173 U3.8
DB_IFC2/FEB3_6: S2.168 U3.9
DB_IFC2/FEB3_7: S2.167 U3.10
DB_IFC2/FEB3_8: S2.162 U3.11
DB_IFC2/FEB3_9: S2.161 U3.12
DB_IFC2/FEB3_10: S2.156 U3.13
DB_IFC2/FEB3_11: S2.155 U3.14
DB_IFC2/FEB3_12: S2.150 U3.15
DB_IFC2/FEB3_13: S2.149 U3.16
DB_IFC2/FEB3_14: S2.144 U3.17
DB_IFC2/FEB3_15: S2.143 U3.18
DB_IFC2/FEB3_16: S2.138 U3.19
DB_IFC2/FEB3_17: S2.137 U3.20
DB_IFC2/FEB3_18: S2.132 U3.21
DB_IFC2/FEB3_19: S2.131 U3.22
DB_IFC2/FEB3_20: S2.126 U3.23
DB_IFC2/FEB3_21: S2.125 U3.24
DB_IFC2/FEB3_22: S2.120 U3.25
DB_IFC2/FEB3_23: S2.119 U3.26
DB_IFC2/FEB3_24: S2.114 U3.27
DB_IFC2/FEB3_25: S2.113 U3.28
DB_IFC2/FEB3_26: S2.108 U3.29
DB_IFC2/FEB3_27: S2.107 U3.30
DB_IFC2/FEB3_28: S2.102 U3.31
DB_IFC2/FEB3_29: S2.101 U3.32
DB_IFC2/FEB3_30: S2.96 U3.33
DB_IFC2/FEB3_31: S2.95 U3.34
DB_IFC2/FEB3_32: S2.90 U3.67
DB_IFC2/FEB3_33: S2.89 U3.68
DB_IFC2/FEB3_34: S2.84 U3.69
DB_IFC2/FEB3_35: S2.83 U3.70
DB_IFC2/FEB3_36: S2.78 U3.71
DB_IFC2/FEB3_37: S2.77 U3.72
DB_IFC2/FEB3_38: S2.72 U3.73
DB_IFC2/FEB3_39: S2.71 U3.74
DB_IFC2/FEB3_40: S2.66 U3.75
DB_IFC2/FEB3_41: S2.65 U3.76
DB_IFC2/FEB3_42: S2.60 U3.77
DB_IFC2/FEB3_43: S2.59 U3.78
DB_IFC2/FEB3_44: S2.54 U3.79
DB_IFC2/FEB3_45: S2.53 U3.80
DB_IFC2/FEB3_46: S2.48 U3.81
DB_IFC2/FEB3_47: S2.47 U3.82
DB_IFC2/FEB3_48: S2.42 U3.83
DB_IFC2/FEB3_49: S2.41 U3.84
DB_IFC2/FEB3_50: S2.36 U3.85
DB_IFC2/FEB3_51: S2.35 U3.86
DB_IFC2/FEB3_52: S2.30(20) U3.87
DB_IFC2/FEB3_53: S2.29 U3.88
DB_IFC2/FEB3_54: S2.24 U3.89
DB_IFC2/FEB3_55: S2.23 U3.90
DB_IFC2/FEB3_56: S2.18 U3.91
DB_IFC2/FEB3_57: S2.17 U3.92
DB_IFC2/FEB3_58: S2.12 U3.93
DB_IFC2/FEB3_59: S2.11 U3.94
DB_IFC2/FEB3_60: S2.6 U3.95
DB_IFC2/FEB3_61: S2.5 U3.96
DB_IFC2/FEB3_62: S2.10 U3.97
DB_IFC2/FEB3_63: S2.4 U3.98
DB_IFC2/FEB4_0: S2.177 U4.3
DB_IFC2/FEB4_1: S2.171 U4.4
DB_IFC2/FEB4_2: S2.175 U4.5
DB_IFC2/FEB4_3: S2.176 U4.6
DB_IFC2/FEB4_4: S2.169 U4.7
DB_IFC2/FEB4_5: S2.170 U4.8
DB_IFC2/FEB4_6: S2.163 U4.9
DB_IFC2/FEB4_7: S2.164 U4.10
DB_IFC2/FEB4_8: S2.157 U4.11
DB_IFC2/FEB4_9: S2.158 U4.12
DB_IFC2/FEB4_10: S2.151 U4.13
DB_IFC2/FEB4_11: S2.152 U4.14
DB_IFC2/FEB4_12: S2.145 U4.15
DB_IFC2/FEB4_13: S2.146 U4.16
DB_IFC2/FEB4_14: S2.139 U4.17
DB_IFC2/FEB4_15: S2.140 U4.18
DB_IFC2/FEB4_16: S2.133 U4.19
DB_IFC2/FEB4_17: S2.134 U4.20
DB_IFC2/FEB4_18: S2.127 U4.21
DB_IFC2/FEB4_19: S2.128 U4.22
DB_IFC2/FEB4_20: S2.121 U4.23
DB_IFC2/FEB4_21: S2.122 U4.24
DB_IFC2/FEB4_22: S2.115 U4.25
DB_IFC2/FEB4_23: S2.116 U4.26
DB_IFC2/FEB4_24: S2.109 U4.27
DB_IFC2/FEB4_25: S2.110 U4.28
DB_IFC2/FEB4_26: S2.103 U4.29
DB_IFC2/FEB4_27: S2.104 U4.30
DB_IFC2/FEB4_28: S2.97 U4.31
DB_IFC2/FEB4_29: S2.98 U4.32
DB_IFC2/FEB4_30: S2.91 U4.33
DB_IFC2/FEB4_31: S2.92 U4.34
DB_IFC2/FEB4_32: S2.85 U4.67
DB_IFC2/FEB4_33: S2.86 U4.68
DB_IFC2/FEB4_34: S2.79 U4.69
DB_IFC2/FEB4_35: S2.80 U4.70
DB_IFC2/FEB4_36: S2.73 U4.71
DB_IFC2/FEB4_37: S2.74 U4.72
DB_IFC2/FEB4_38: S2.67 U4.73
DB_IFC2/FEB4_39: S2.68 U4.74
DB_IFC2/FEB4_40: S2.61 U4.75
DB_IFC2/FEB4_41: S2.62 U4.76
DB_IFC2/FEB4_42: S2.55 U4.77
DB_IFC2/FEB4_43: S2.56 U4.78
DB_IFC2/FEB4_44: S2.49 U4.79
DB_IFC2/FEB4_45: S2.50 U4.80
DB_IFC2/FEB4_46: S2.43 U4.81
DB_IFC2/FEB4_47: S2.44 U4.82
DB_IFC2/FEB4_48: S2.37 U4.83
DB_IFC2/FEB4_49: S2.38 U4.84
DB_IFC2/FEB4_50: S2.31 U4.85
DB_IFC2/FEB4_51: S2.32 U4.86
DB_IFC2/FEB4_52: S2.25 U4.87
DB_IFC2/FEB4_53: S2.26 U4.88
DB_IFC2/FEB4_54: S2.19 U4.89
DB_IFC2/FEB4_55: S2.20 U4.90
DB_IFC2/FEB4_56: S2.13 U4.91
DB_IFC2/FEB4_57: S2.14 U4.92
DB_IFC2/FEB4_58: S2.7 U4.93
DB_IFC2/FEB4_59: S2.8 U4.94
DB_IFC2/FEB4_60: S2.1 U4.95
DB_IFC2/FEB4_61: S2.2 U4.96
DB_IFC2/FEB4_62: S2.9 U4.97
DB_IFC2/FEB4_63: S2.3 U4.98
DB_IFC2/H3_En0: U3.48 U13.13(IO10)
DB_IFC2/H3_En1: U3.50 U13.14(IO11)
DB_IFC2/H3_En2: U3.52 U13.15(IO12)
DB_IFC2/H3_En3: U3.54 U13.16(IO13)
DB_IFC2/H3_En4: U3.37 U13.17(IO14)
DB_IFC2/H3_En5: U3.45 U13.18(IO15)
DB_IFC2/H3_En6: U3.47 U13.19(IO16)
DB_IFC2/H3_En7: U3.49 U13.20(IO17)
DB_IFC2/H4_En0: U4.48 U13.4(IO0)
DB_IFC2/H4_En1: U4.50 U13.5(IO1)
DB_IFC2/H4_En2: U4.52 U13.6(IO2)
DB_IFC2/H4_En3: U4.54 U13.7(IO3)
DB_IFC2/H4_En4: U4.37 U13.8(IO4)
DB_IFC2/H4_En5: U4.45 U13.9(IO5)
DB_IFC2/H4_En6: U4.47 U13.10(IO6)
DB_IFC2/H4_En7: U4.49 U13.11(IO7)
DB_IFC2/I2C_SCL: R46.2 R53.1 R56.1 R63.1 S2.99
DB_IFC2/I2C_SDA: R45.2 R52.1 R57.1 R64.1 S2.93
DB_IFC2/MISC_IO<14>: S2.159
DB_IFC2/MISO: R33.2 R38.2 R40.2 R42.2 S2.21
DB_IFC2/MOSI: U3.46 U4.46 U15.4(O)
DB_IFC2/nSEL: U3.62 U4.62 U14.4(O)
DB_IFC2/SCLK: U3.56 U4.56 U16.4(O)
DB_IFC2/SEU_D: R34.2 R39.2 R41.2 R43.2 S2.27
DB_IFC2/SEU_GenEn: S2.39 U3.40 U4.40
DB_IFC2/spi_clk: S2.69 U16.2(I)
DB_IFC2/spi_dat: S2.75 U15.2(I)
DB_IFC2/spi_nSEL: S2.81 U14.2(I)
DB_IFC2/Test_level: R49.2 U3.63 U4.63
DB_IFC2/TESTD2<33_64>: S2.141
DB_IFC2/TestPulse: S2.153 U3.61 U4.61
DB_IFC2/TSens_GND: R37.1 U4.53
DB_IFC2/TSens_SCL: R46.1 R47.1 U3.53
DB_IFC2/TSens_SDA: R44.1 R45.1 U3.51
DB_IFC2/TSens_VDD: R35.1 R36.1 U4.51
FE_2V5: C4.1 C8.1 R7.1 R8.1 R15.2 R36.2 R38.1 R39.1 S1.33 S1.34 S1.123 S1.124 S1.147 S1.148 S2.33 S2.34 S2.123 S2.124 S2.147 S2.148 U8.5(VCC) U9.5(VCC) U10.5(VCC) U14.5(VCC) U15.5(VCC) U16.5(VCC)
DB_IFC1/N13946323: R17.1 R19.2 U5.4(out)
DB_IFC1/N13946657: R18.2 R19.1 U5.3(-)
DB_IFC1/N13947191: R1.1 U1.44
DB_IFC1/N13947431: R22.2 R23.2 U6.6(A0)
DB_IFC1/N13947777: R32.2 U7.23(SDA)
DB_IFC1/N13947787: R31.2 U7.22(SCL)
DB_IFC1/N13947851: R26.2 R27.2 U7.21(A0)
DB_IFC1/N13947963: R28.2 U7.2(A1)
DB_IFC1/N13947967: R29.2 U7.3(A2)
DB_IFC1/N13948023: R30.2 U7.1(nINT)
DB_IFC1/N13948277: R16.2 U5.1(+)
DB_IFC1/N13948631: R20.2 U6.4(SDA)
DB_IFC1/N13948635: R21.2 U6.5(SCL)
DB_IFC1/N13966514: R2.1 U1.39
DB_IFC1/N13975140: R11.1 U2.44
DB_IFC1/N13975216: R12.1 U2.39
DB_IFC2/N13982229: R49.1 R51.2 U11.4(out)
DB_IFC2/N13982293: R50.2 R51.1 U11.3(-)
DB_IFC2/N13982301: R33.1 U4.44
DB_IFC2/N13982333: R54.2 R55.2 U12.6(A0)
DB_IFC2/N13982425: R64.2 U13.23(SDA)
DB_IFC2/N13982429: R63.2 U13.22(SCL)
DB_IFC2/N13982433: R58.2 R59.2 U13.21(A0)
DB_IFC2/N13982453: R60.2 U13.2(A1)
DB_IFC2/N13982455: R61.2 U13.3(A2)
DB_IFC2/N13982469: R62.2 U13.1(nINT)
DB_IFC2/N13982547: R48.2 U11.1(+)
DB_IFC2/N13982629: R52.2 U12.4(SDA)
DB_IFC2/N13982631: R53.2 U12.5(SCL)
DB_IFC2/N13982797: R34.1 U4.39
DB_IFC2/N13982825: R42.1 U3.44
DB_IFC2/N13982847: R43.1 U3.39

Not connected (* = marked no-connect by the designer): S1 22* 28* 40* 64* 70* 76* 82* 94* 100* 106* 112* 142* 154* 160* 181(MH1)* 182(MH2)*; S2 22* 28* 40* 64* 70* 76* 82* 94* 100* 106* 112* 142* 154* 160* 181(MH1)* 182(MH2)*; U1 55 64 101(MH1)* 102(MH2)*; U2 55 64 101(MH1)* 102(MH2)*; U3 55 64 101(MH1)* 102(MH2)*; U4 55 64 101(MH1)* 102(MH2)*

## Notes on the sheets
sheet 1
- SEAM-30-02.0-L-06-2-A-K
- p175
- p180
- S1
- p1
- p6
- p1
- p6
- H1
- p99
- S2
- p180
- p100
- H2
- p175
- H3
- p1
- HSEC8_150_01_L_DV_A_K
- p2
- H4
- J4
- FEB BOT
- p1
- J3
- J6
- p39
- J8
- p40
- J7
- p2
sheet 2
- J1
- J2
- J5
- J6
- BASEBOARD (VIEW FROM PMT SIDE)
- PMT_A
- PMT_C
- U3 - TEMP MEAS
- U4 - TEMP MEAS
- SEAM-30-02.0-L-06-2-A-K
- p175
- p180
- S1
- p1
- p6
- PMT_B
- PMT_D
- p6
- p1
- H1
- p99
- S2
- p180
- p100
- H2
- J4
- J3
- J8
- J7
- p175
- H3
- p1
- HSEC8_150_01_L_DV_A_K
- p2
- H4
- J4
- FEB BOT
- p1
- J3
- p100
- J6
- p2
- p39
- J8
- p40
- FEB: BOTTOM SIDE
- J7
- p2
sheet 3
- for FEB plugging into baseboard connectors J4,J1
- former definitions:
- --->
- MISC_IO<1>
- (opt)
- --->
- MISC_IO<2>
- (opt)
- <---
- TESTD1<33_64>
- SEU detected flag;
  active HIGH; optional
- (opt)
- <---
- TESTD2<1_32>
- spi_rst
- <--->
- MISC_IO<10>
- <---
- MISC_IO<11>
- for FEB plugging into baseboard connectors J3,J2
- <---
- TESTD1<1_32>
sheet 4
- 1
- 51
- 2
- Denomination on FEB:
- SEU_clk
- 27
- Chain_E1
- Chain_E2
- Chain_E3
- 27
- 77
- Chain_E4
- 28
- 78
- 50
- 100
sheet 5
- 1
- 51
- 2
- Denomination on FEB:
- SEU_clk
- 27
- Chain_E1
- Chain_E2
- Chain_E3
- 27
- 77
- Chain_E4
- 28
- 78
- 50
- 100
sheet 6
- for FEB plugging into baseboard connectors J7,J6
- --->
- former definitions:
- (opt)
- --->
- MISC_IO<1>
- MISC_IO<2>
- (opt)
- <---
- TESTD1<33_64>
- SEU detected flag;
  active HIGH; optional
- (opt)
- <---
- TESTD2<1_32>
- spi_rst
- <--->
- <---
- MISC_IO<10>
- MISC_IO<11>
- for FEB plugging into baseboard connectors J8,J5
- <---
- TESTD1<1_32>
sheet 7
- 1
- 51
- 2
- Denomination on FEB:
- SEU_clk
- 27
- Chain_E1
- Chain_E2
- Chain_E3
- 27
- 77
- Chain_E4
- 28
- 78
- 50
- 100
sheet 8
- 1
- 51
- 2
- Denomination on FEB:
- SEU_clk
- 27
- Chain_E1
- Chain_E2
- Chain_E3
- 27
- 77
- Chain_E4
- 28
- 78
- 50
- 100
